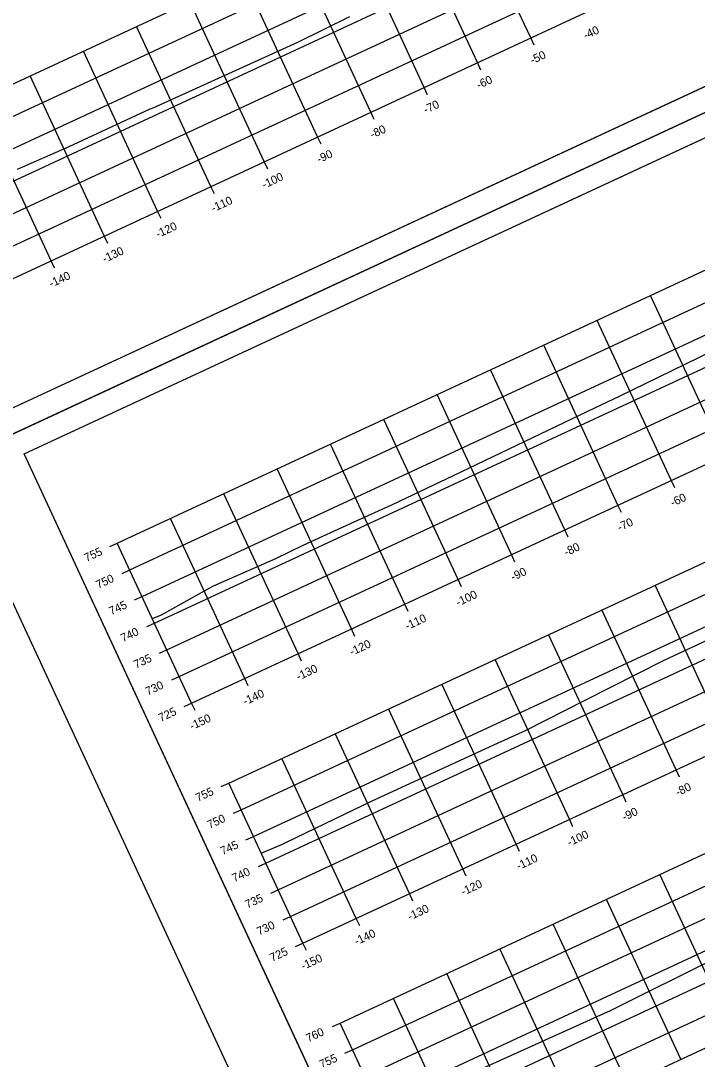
# Model space of a CAD drawing. Extents: x 1354696 to 1366163, y 660729 to 670380.
# Drawn here: x 1356702.3 to 1356817.4, y 664743.4 to 664920 of the extents above; entities that cross this region are included whole.
import ezdxf

# ---------------------------------------------------------------- set-up
doc = ezdxf.new("R2010")
doc.units = 0
for name, color, linetype in [('R_Axis', 7, 'Continuous'), ('R_Axis Annot', 7, 'Continuous'), ('R_Border', 7, 'Continuous'), ('R_Exist Surface', 7, 'Continuous'), ('R_Grid', 7, 'Continuous'), ('R_No Plot', 7, 'Continuous')]:
    doc.layers.add(name, color=color, linetype=linetype)

msp = doc.modelspace()

# ---------------------------------------------------------------- linework, layer by layer
at = {"layer": 'R_Axis'}
for p, q in [((1356698.35, 664874.98), (1356970.45, 665001.31)), ((1356731.33, 664803.93), (1357003.44, 664930.26)), ((1356789.64, 664915.82), (1356789.05, 664917.09)), ((1356780.57, 664911.61), (1356779.98, 664912.88)), ((1356771.5, 664907.4), (1356770.91, 664908.67)), ((1356762.43, 664903.19), (1356761.84, 664904.46)), ((1356753.36, 664898.98), (1356752.77, 664900.25)), ((1356744.29, 664894.77), (1356743.7, 664896.04)), ((1356735.22, 664890.56), (1356734.63, 664891.83)), ((1356750.28, 664763.11), (1357022.39, 664889.44)), ((1356726.15, 664886.35), (1356725.56, 664887.62)), ((1356717.07, 664882.13), (1356716.49, 664883.4)), ((1356708, 664877.92), (1356707.42, 664879.19)), ((1356769.23, 664722.3), (1357041.34, 664848.63)), ((1356813.55, 664840.56), (1356812.96, 664841.83)), ((1356804.48, 664836.35), (1356803.89, 664837.62)), ((1356795.41, 664832.14), (1356794.82, 664833.41)), ((1356717.43, 664830.55), (1356718.7, 664831.14)), ((1356731.33, 664803.93), (1356718.7, 664831.14)), ((1356786.34, 664827.93), (1356785.75, 664829.2)), ((1356719.54, 664826.01), (1356720.81, 664826.6)), ((1356777.27, 664823.71), (1356776.68, 664824.98)), ((1356721.64, 664821.48), (1356722.91, 664822.07)), ((1356768.2, 664819.5), (1356767.61, 664820.77)), ((1356723.75, 664816.94), (1356725.02, 664817.53)), ((1356759.13, 664815.29), (1356758.54, 664816.56)), ((1356725.85, 664812.41), (1356727.12, 664813)), ((1356750.06, 664811.08), (1356749.47, 664812.35)), ((1356727.96, 664807.87), (1356729.23, 664808.46)), ((1356740.99, 664806.87), (1356740.4, 664808.14)), ((1356730.06, 664803.34), (1356731.33, 664803.93)), ((1356731.92, 664802.66), (1356731.33, 664803.93)), ((1356814.36, 664791.32), (1356813.77, 664792.59)), ((1356736.38, 664789.73), (1356737.65, 664790.32)), ((1356750.28, 664763.11), (1356737.65, 664790.32)), ((1356805.29, 664787.11), (1356804.7, 664788.38)), ((1356738.49, 664785.2), (1356739.76, 664785.79)), ((1356796.22, 664782.9), (1356795.63, 664784.17)), ((1356740.59, 664780.66), (1356741.86, 664781.25)), ((1356787.15, 664778.69), (1356786.56, 664779.96)), ((1356742.7, 664776.13), (1356743.97, 664776.72)), ((1356778.08, 664774.48), (1356777.49, 664775.75)), ((1356744.8, 664771.59), (1356746.07, 664772.18)), ((1356769.01, 664770.27), (1356768.42, 664771.54)), ((1356746.91, 664767.06), (1356748.18, 664767.65)), ((1356759.94, 664766.05), (1356759.35, 664767.32)), ((1356749.01, 664762.52), (1356750.28, 664763.11)), ((1356750.87, 664761.84), (1356750.28, 664763.11)), ((1356755.33, 664748.92), (1356756.6, 664749.51)), ((1356769.23, 664722.3), (1356756.6, 664749.51)), ((1356757.44, 664744.38), (1356758.71, 664744.97))]:
    msp.add_line(p, q, dxfattribs=at)
at = {"layer": 'R_Border'}
for p, q in [((1356986.29, 664986.62), (1356699.51, 664853.47)), ((1356702.83, 664846.33), (1356989.61, 664979.47)), ((1356789.35, 664659.97), (1356702.83, 664846.33))]:
    msp.add_line(p, q, dxfattribs=at)
at = {"layer": 'R_Exist Surface'}
for points in [[(1356701.71, 664894.77), (1356710.5, 664898.61), (1356724.31, 664905), (1356724.54, 664905.1), (1356724.78, 664905.21), (1356749.43, 664916.33), (1356758.29, 664920.7)], [(1356724.66, 664818.31), (1356726.2, 664818.97), (1356734.95, 664823.84), (1356745.65, 664828.51), (1356750.35, 664830.78), (1356758.98, 664834.75), (1356765.52, 664837.74), (1356775.93, 664842.63), (1356798.76, 664853.6), (1356804.27, 664856.21), (1356808.57, 664858.28), (1356827.05, 664867.33)], [(1356743.19, 664778.39), (1356746.78, 664779.93), (1356747.51, 664780.26), (1356762.06, 664787.31), (1356782.76, 664796.83), (1356788.24, 664799.35), (1356798.19, 664804.39), (1356811.73, 664811.26), (1356820.77, 664815.46)], [(1356775.6, 664739.48), (1356800.95, 664750.89), (1356802.64, 664751.67), (1356820.95, 664760.77)]]:
    msp.add_lwpolyline(points, dxfattribs=at)
at = {"layer": 'R_Grid'}
for p, q in [((1356685.71, 664902.19), (1356957.82, 665028.52)), ((1356687.82, 664897.66), (1356959.92, 665023.99)), ((1356689.92, 664893.12), (1356962.03, 665019.45)), ((1356692.03, 664888.59), (1356964.13, 665014.92)), ((1356694.13, 664884.05), (1356966.24, 665010.38)), ((1356696.24, 664879.52), (1356968.34, 665005.85)), ((1356698.35, 664874.98), (1356970.45, 665001.31)), ((1356718.7, 664831.14), (1356990.8, 664957.47)), ((1356720.81, 664826.6), (1356992.91, 664952.93)), ((1356722.91, 664822.07), (1356995.02, 664948.4)), ((1356725.02, 664817.53), (1356997.12, 664943.86)), ((1356789.05, 664917.09), (1356776.41, 664944.3)), ((1356727.12, 664813), (1356999.23, 664939.33)), ((1356779.98, 664912.88), (1356767.34, 664940.09)), ((1356770.91, 664908.67), (1356758.27, 664935.88)), ((1356729.23, 664808.46), (1357001.33, 664934.79)), ((1356761.84, 664904.46), (1356749.2, 664931.67)), ((1356731.33, 664803.93), (1357003.44, 664930.26)), ((1356752.77, 664900.25), (1356740.13, 664927.46)), ((1356743.7, 664896.04), (1356731.06, 664923.25)), ((1356734.63, 664891.83), (1356721.99, 664919.04)), ((1356737.65, 664790.32), (1357009.75, 664916.65)), ((1356725.56, 664887.62), (1356712.92, 664914.83)), ((1356739.76, 664785.79), (1357011.86, 664912.12)), ((1356716.49, 664883.4), (1356703.85, 664910.62)), ((1356741.86, 664781.25), (1357013.97, 664907.58)), ((1356707.42, 664879.19), (1356694.78, 664906.4)), ((1356743.97, 664776.72), (1357016.07, 664903.05)), ((1356746.07, 664772.18), (1357018.18, 664898.51)), ((1356748.18, 664767.65), (1357020.28, 664893.98)), ((1356750.28, 664763.11), (1357022.39, 664889.44)), ((1356756.6, 664749.51), (1357028.7, 664875.84)), ((1356822.03, 664846.04), (1356809.4, 664873.25)), ((1356758.71, 664744.97), (1357030.81, 664871.3)), ((1356812.96, 664841.83), (1356800.33, 664869.04)), ((1356760.81, 664740.44), (1357032.91, 664866.77)), ((1356803.89, 664837.62), (1356791.26, 664864.83)), ((1356762.92, 664735.9), (1357035.02, 664862.23)), ((1356794.82, 664833.41), (1356782.19, 664860.62)), ((1356765.02, 664731.37), (1357037.13, 664857.7)), ((1356785.75, 664829.2), (1356773.12, 664856.41)), ((1356767.13, 664726.83), (1357039.23, 664853.16)), ((1356776.68, 664824.98), (1356764.05, 664852.19)), ((1356767.61, 664820.77), (1356754.98, 664847.98)), ((1356769.23, 664722.3), (1357041.34, 664848.63)), ((1356758.54, 664816.56), (1356745.91, 664843.77)), ((1356749.47, 664812.35), (1356736.84, 664839.56)), ((1356740.4, 664808.14), (1356727.77, 664835.35)), ((1356731.33, 664803.93), (1356718.7, 664831.14)), ((1356822.84, 664796.8), (1356810.21, 664824.01)), ((1356813.77, 664792.59), (1356801.14, 664819.8)), ((1356804.7, 664788.38), (1356792.07, 664815.59)), ((1356795.63, 664784.17), (1356783, 664811.38)), ((1356786.56, 664779.96), (1356773.93, 664807.17)), ((1356777.49, 664775.75), (1356764.86, 664802.96)), ((1356768.42, 664771.54), (1356755.79, 664798.75)), ((1356759.35, 664767.32), (1356746.72, 664794.53)), ((1356750.28, 664763.11), (1356737.65, 664790.32)), ((1356823.65, 664747.56), (1356811.02, 664774.77)), ((1356814.58, 664743.35), (1356801.95, 664770.56)), ((1356805.51, 664739.14), (1356792.88, 664766.35)), ((1356796.44, 664734.93), (1356783.81, 664762.14)), ((1356787.37, 664730.72), (1356774.74, 664757.93)), ((1356778.3, 664726.51), (1356765.67, 664753.72)), ((1356769.23, 664722.3), (1356756.6, 664749.51))]:
    msp.add_line(p, q, dxfattribs=at)
at = {"layer": 'R_No Plot'}
msp.add_line((1356689.94, 664844.64), (1356992.28, 664985.01), dxfattribs=at)
msp.add_line((1356689.94, 664844.64), (1356992.28, 664985.01), dxfattribs=at)
for points in [[(1356600.1, 665038.14), (1356902.44, 665178.51), (1356992.28, 664985.01), (1356689.93, 664844.64)], [(1356825.16, 665138.33), (1356842.96, 665146.59), (1356847.12, 665137.63), (1356861.73, 665144.42), (1356882.77, 665154.19), (1356894.74, 665128.7), (1356915.79, 665138.47), (1356986.29, 664986.62), (1356699.51, 664853.47), (1356612.99, 665039.83)], [(1356689.93, 664844.64), (1356992.28, 664985.01), (1357082.12, 664791.51), (1356779.77, 664651.14)], [(1356915, 664944.83), (1356932.79, 664953.09), (1356936.95, 664944.13), (1356951.57, 664950.92), (1356972.61, 664960.69), (1356984.58, 664935.2), (1357005.63, 664944.97), (1357076.13, 664793.12), (1356789.35, 664659.97), (1356702.83, 664846.33)]]:
    msp.add_lwpolyline(points, close=True, dxfattribs=at)

# ---------------------------------------------------------------- texts
at = {"layer": 'R_Axis Annot'}
for s, p in [('-40', (1356798.38, 664916.8)), ('-50', (1356789.31, 664912.58)), ('-60', (1356780.21, 664908.36)), ('-70', (1356771.17, 664904.16)), ('-80', (1356762.1, 664899.95)), ('-90', (1356753.03, 664895.74)), ('-100', (1356743.7, 664891.41)), ('-110', (1356735.04, 664887.39)), ('-120', (1356725.61, 664883.01)), ('-130', (1356716.54, 664878.8)), ('-140', (1356707.47, 664874.59)), ('-60', (1356813.2, 664837.31)), ('-70', (1356804.16, 664833.11)), ('755', (1356713.46, 664827.93)), ('-80', (1356795.09, 664828.9)), ('-90', (1356786.02, 664824.69)), ('750', (1356715.45, 664823.35)), ('-100', (1356776.69, 664820.36)), ('745', (1356717.67, 664818.86)), ('-110', (1356768.03, 664816.33)), ('740', (1356719.66, 664814.28)), ('-120', (1356758.6, 664811.96)), ('735', (1356721.88, 664809.79)), ('-130', (1356749.53, 664807.75)), ('730', (1356723.87, 664805.21)), ('-140', (1356740.46, 664803.53)), ('725', (1356726.09, 664800.72)), ('-150', (1356731.39, 664799.32)), ('755', (1356732.41, 664787.12)), ('-80', (1356814.04, 664788.08)), ('-90', (1356804.97, 664783.87)), ('750', (1356734.4, 664782.53)), ('-100', (1356795.64, 664779.54)), ('745', (1356736.62, 664778.05)), ('-110', (1356786.98, 664775.52)), ('740', (1356738.61, 664773.46)), ('-120', (1356777.55, 664771.14)), ('735', (1356740.83, 664768.98)), ('-130', (1356768.48, 664766.93)), ('730', (1356742.82, 664764.39)), ('-140', (1356759.41, 664762.72)), ('725', (1356745.04, 664759.91)), ('-150', (1356750.34, 664758.51)), ('760', (1356751.19, 664746.22)), ('755', (1356753.46, 664741.77))]:
    msp.add_text(s, height=1.4, rotation=24.9042, dxfattribs=at).set_placement(p)

doc.saveas('drawing.dxf')
